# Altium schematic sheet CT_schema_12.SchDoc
size 277 x 170 mm
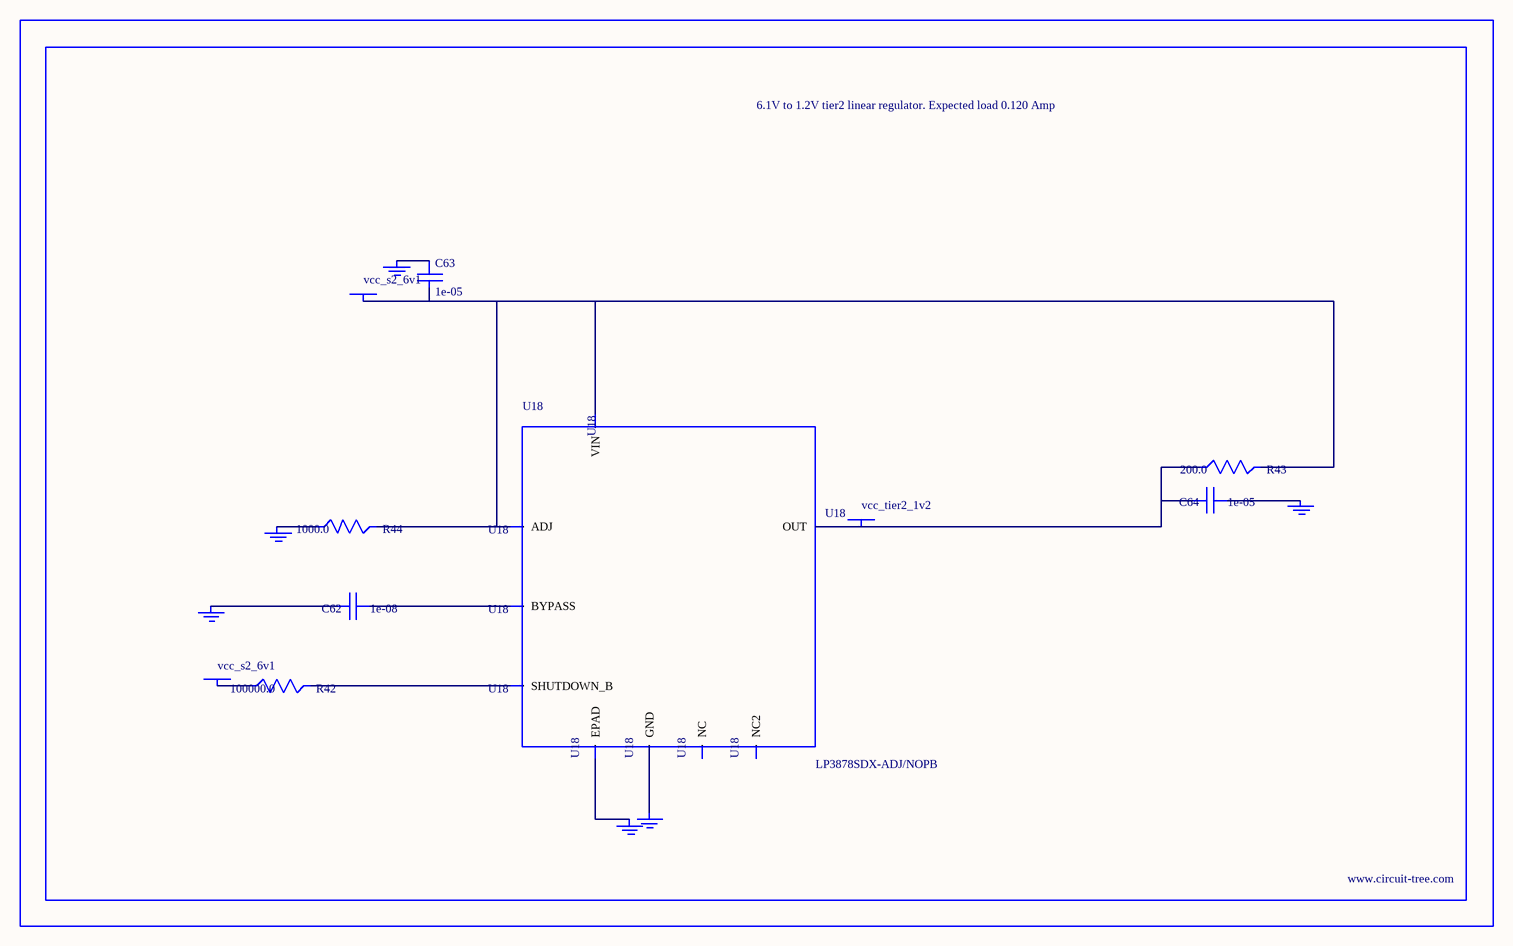
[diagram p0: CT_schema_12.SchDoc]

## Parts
BORDER11  (no value)
C62  1e-08  [C0402]
C63  1e-05  [C1206]
C64  1e-05  [C0805]
GND_INSTANCE_11_0  (no value)
GND_INSTANCE_11_1  (no value)
GND_INSTANCE_11_2  (no value)
GND_INSTANCE_11_3  (no value)
GND_INSTANCE_11_4  (no value)
GND_INSTANCE_11_5  (no value)
POWER_INSTANCE_11_0  vcc_s2_6v1
POWER_INSTANCE_11_1  vcc_s2_6v1
POWER_INSTANCE_11_2  vcc_tier2_1v2
R42  100000.0  [R0603]
R43  200.0  [R0603]
R44  1000.0  [R0603]
U18  LP3878SDX-ADJ/NOPB  [WSON-8]

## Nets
NetC62_1: C62.1 U18.1(BYPASS)
NetC62_2: C62.2 GND_INSTANCE_11_0.0(GND)
NetC63_1: C63.1 GND_INSTANCE_11_1.0(GND)
NetC63_2: C63.2 POWER_INSTANCE_11_0.0(PWR) R43.2 R44.2 U18.4(VIN) U18.6(ADJ)
NetC64_1: C64.1 GND_INSTANCE_11_2.0(GND)
NetC64_2: C64.2 POWER_INSTANCE_11_2.0(PWR) R43.1 U18.5(OUT)
NetGND_INSTANCE_11_3_0: GND_INSTANCE_11_3.0(GND) R44.1
NetGND_INSTANCE_11_4_0: GND_INSTANCE_11_4.0(GND) U18.PAD(EPAD)
NetGND_INSTANCE_11_5_0: GND_INSTANCE_11_5.0(GND) U18.3(GND)
NetPOWER_INSTANCE_11_1_0: POWER_INSTANCE_11_1.0(PWR) R42.1
NetR42_2: R42.2 U18.8(SHUTDOWN_B)

Not connected (* = marked no-connect by the designer): U18 2(NC) 7(NC2)

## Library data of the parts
BORDER11 = BORDER_PAGE11
C62 = C0402C103K3RAC
C63 = C1206C106K3RACTU
C64 = GRM219R60J106ME19D
GND_INSTANCE_11_0-GND_INSTANCE_11_5 = GND
POWER_INSTANCE_11_0-POWER_INSTANCE_11_2 = PWR
R42 = RC0603JR-07100KL
R43 = RC0603JR-07200RL
R44 = RC0603JR-071KL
